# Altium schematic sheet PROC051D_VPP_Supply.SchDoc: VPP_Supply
size 431 x 279 mm; Date: Not shown in title block; ApprovedBy: Not shown in title block; CheckedBy: Not shown in title block; Author: Not shown in title block; CompanyName: Not shown in title block; Engineer: Not shown in title block; Organization: Not shown in title block; Address1: Not shown in title block; Address2: Not shown in title block; Address3: Not shown in title block; Address4: Not shown in title block; DocumentNumber: 9; Revision: Use project parameter SCH_Rev; SheetNumber: 9; SheetTotal: 16; PageSetup: Record=PageOptions¦CenterHorizontal=True¦CenterVertical=True¦PrintScale=1.00¦XCorrection=1.00¦YCorrection=1.00¦PrintKind=0¦BorderSize=5000000¦LeftOffset=0¦BottomOffset=0¦Orientation=2¦PaperLength=1000¦PaperWidth=1000¦Scale=100¦PaperSource=15¦PrintQuality=600¦MediaType=1¦DitherType=10¦PaperKind=Letter¦PrintScaleMode=1
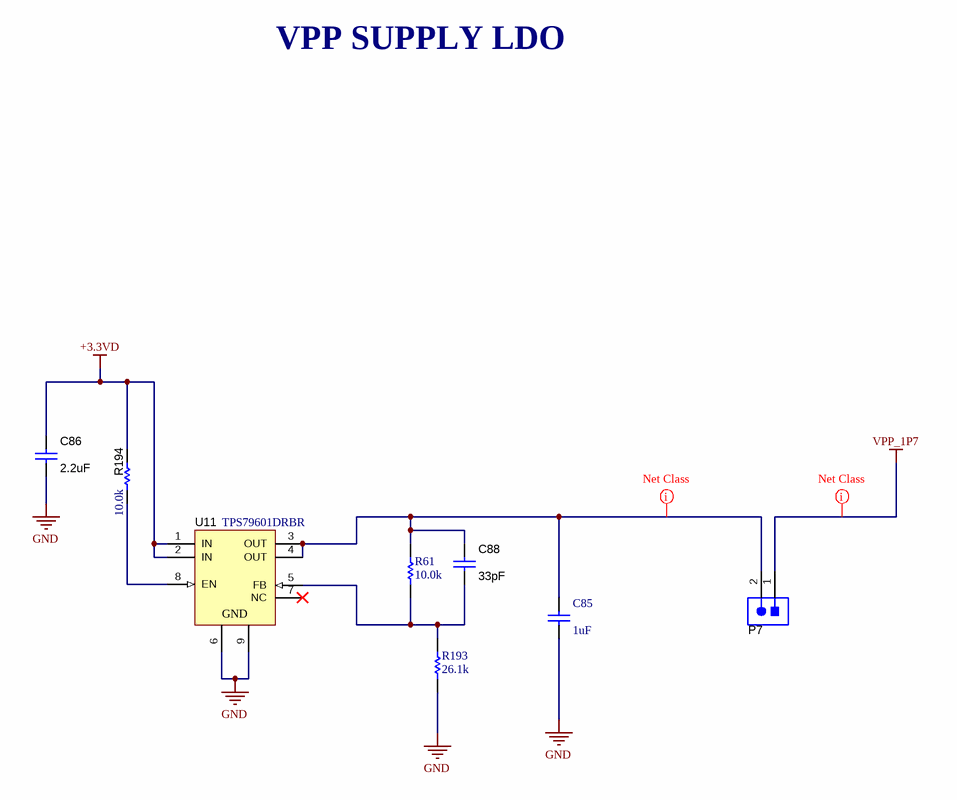
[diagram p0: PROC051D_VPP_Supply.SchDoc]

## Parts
C85  ValueDisplayed: 1uF  [0402]  (hidden comment: GRM155R70J105MA12D)
C86  ValueDisplayed: 2.2uF  [0402_065L]  (hidden comment: C1005X7S1A225K050BC)
C88  ValueDisplayed: 33pF  [0402L]  (hidden comment: C0402C330J5GAC)
P7  TSW-102-07-G-S  [TSW-102-07-G-S]  (value not drawn)
R61  ValueDisplayed: 10.0k  [0402]  (hidden comment: ERJ-2RKF1002X)
R193  ValueDisplayed: 26.1k  [0402]  (hidden comment: CRCW040226K1FKED)
R194  ValueDisplayed: 10.0k  [0402L]  (hidden comment: CRCW040210K0FKED)
U11  TPS79601DRBR  [DRB0008B]

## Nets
+3.3VD: C86.2 R194.1 U11.1(IN) U11.2(IN)
GND: C85.2 C86.1 R193.1 U11.6(GND) U11.9(GND)
VPP_1P7: P7.1
NetC85_1: C85.1 C88.1 P7.2 R61.2 U11.3(OUT) U11.4(OUT)
NetC88_2: C88.2 R61.1 R193.2 U11.5(FB)
NetR194_2: R194.2 U11.8(EN)

Not connected (* = marked no-connect by the designer): U11 7(NC)*

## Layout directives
net class PWR: NetC85_1, VPP_1P7

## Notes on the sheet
- VPP SUPPLY LDO

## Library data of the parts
C85 = CMP-0006624-2: CAP, CERM, 1 uF, 6.3 V, +/- 20%, X7R, 0402; Manufacturer: MuRata; TaMin_C: -55°C; Polarized: N; SizeAreaWB_mm2: 3; Value1: Unknown; U/M: EA; Value: 1uF; TaMax_C: 125°C; SizeZ_mm: 0.6; SizeX_mm: 1; SizeY_mm: 0.5; Value2: 6.3V; Cap_F: 1µF; AEC Category: Q200
C86 = CMP-0006302-2: CAP, CERM, 2.2 uF, 10 V, +/- 10%, X7S, 0402; Manufacturer: TDK; TaMin_C: -55°C; ESR_ohm: 5.925m; Polarized: N; SizeAreaWB_mm2: 3; Value1: 0.005925 ohm; U/M: EA; Value: 2.2uF; TaMax_C: 125°C; SizeZ_mm: 0.65; SizeX_mm: 1; SizeY_mm: 0.5; Cap_Case: 0402_065; Value2: 10V; CompType: Capacitor; Cap_F: 2.2µF; IRMS_A: 2.05591A; AEC Category: Q200
C88 = CMP-0006242-2: CAP, CERM, 33 pF, 50 V, +/- 5%, C0G/NP0, 0402; Manufacturer: Kemet; TaMin_C: -55°C; Polarized: N; SizeAreaWB_mm2: 3; Value1: Unknown; U/M: EA; Value: 33pF; TaMax_C: 125°C; SizeZ_mm: 0.6; SizeX_mm: 1; SizeY_mm: 0.5; Cap_Case: 0402; Value2: 50V; AEC Category: Q200
P7 = CMP-0075405-2: Header, 100mil, 2x1, Gold, TH; Manufacturer: Samtec; Pitch_mm: 2.54; Cert_VDE: N; Gender: Male; Cert_CSA: Y; Voltage_V: 550V; Green_REACh: Passed; Current_A: 6.3A; Green_Lifecycle: Active; Row_Count: 1
R61 = CMP-0026658-1: RES, 10.0 k, 1%, 0.1 W, 0402; Manufacturer: Panasonic; Power_W: 100mW; TempCo: 100 ppm/C; Value_Code: 10k0; U/M: EA; Value: 10.0k; EIA_Code: E96; Res_ohm: 10k; SizeX_mm: 1; SizeY_mm: 0.5; SizeZ_mm: 0.6; Value2: 0.1W; VDC_V: 50V; AEC Category: Q200
R193 = CMP-0026207-2: RES, 26.1 k, 1%, 0.063 W, AEC-Q200 Grade 0, 0402; Manufacturer: Vishay-Dale; Power_W: 63mW; TempCo: 100 ppm/C; Value_Code: 26k1; Value: 26.1k; EIA_Code: E96; SizeX_mm: 1; SizeY_mm: 0.5; SizeZ_mm: 0.6; Value2: 0.063W; AEC Qualified: Y; VDC_V: 50V; AEC Category: Q200; AEC Grade: 0
R194 = CMP-0025958-3: RES, 10.0 k, 1%, 0.063 W, AEC-Q200 Grade 0, 0402; Manufacturer: Vishay-Dale; Power_W: 63mW; TempCo: 100 ppm/C; Value_Code: 10k0; Value: 10.0k; EIA_Code: E96; Res_ohm: 10k; SizeX_mm: 1; SizeY_mm: 0.5; SizeZ_mm: 0.6; Value2: 0.063W; AEC Qualified: Y; VDC_V: 50V; AEC Category: Q200; AEC Grade: 0
U11 = CMP-0036402-3: Single Output High PSRR LDO, 1 A, Adjustable 1.2 to 5.5 V Output, 2.7 to 5.5 V Input, 8-pin SON (DRB), -40 to 125 degC, Green (RoHS & no Sb/Br); Manufacturer: Texas Instruments; Vin(Min)(V): 2.7; Vout Adj(Max)(V): 5.5; Vout Adj(Min)(V): 1.2; Accuracy(%): 2; SubFamily: Single Channel LDO; Iq(Typ)(mA): 0.26; Vdo(Typ)(mV): 250; Iout(Max)(A): 1; AEC Category: Q200; AEC Qualified: N; CompType: IC; SizeArea_mm2: 9.0; SizeAreaWB_mm2: 16.0; SizeX_mm: 3.0; SizeZ_mm: 1.0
